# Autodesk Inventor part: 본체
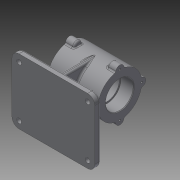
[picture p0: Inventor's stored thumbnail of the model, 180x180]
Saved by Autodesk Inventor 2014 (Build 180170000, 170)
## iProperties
Created: 2015-12
Part Number: 본체
Material: Generic
Document SubType Name: Modeling
Designer: test_25
Density: 1 g/cm^3
Appearance: Default
Author: test_25
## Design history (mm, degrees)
sketch "스케치3"
  geometry: L1 (-42.5, 37)-(42.5, 37); L2 (42.5, 37)-(42.5, 23.5); L3 (42.5, 23.5)-(20.5, 23.5); L4 (20.5, 23.5)-(20.5, 21); L5 (20.5, 21)-(-20.5, 21); L6 (-20.5, 21)-(-20.5, 23.5); L7 (-20.5, 23.5)-(-42.5, 23.5); L8 (-42.5, 23.5)-(-42.5, 37); L9 (-42.5, 0)-(42.5, 0); 2 further points
  constraints: 18 end point, 4 horizontal, 3 vertical, 2 perpendicular, 2 vertical alignment, 1 coincident, 1 midpoint
  dimensions: "d0" = 85 distance of L1.start L1.end; "d1" = 22 distance of L6.end L7.end; "d2" = 41 distance of L4.end L5.end; "d3" = 47 diameter of L7 L9; "d4" = 42 diameter of L5 L9; "d5" = 47 diameter of L3 L9; "d6" = 74 diameter of L1 L9
revolve "회전1" sketch "스케치3" stored, may be unused: angle "d7" = 90 deg
node "작업 평면1"
sketch "스케치4"
  geometry: L1 (-68, 55)-(48, 55); L2 (60, 43)-(60, -43); L3 (48, -55)-(-68, -55); L4 (-80, -43)-(-80, 43); A1 r 12 centre (-68, 43) between (-68, 55) and (-80, 43); A2 r 12 centre (-68, -43) between (-80, -43) and (-68, -55); A3 r 12 centre (48, -43) between (48, -55) and (60, -43); A4 r 12 centre (48, 43) between (60, 43) and (48, 55); 4 further points
  constraints: 8 end point, 8 point on circle, 8 tangent, 6 point on line, 4 centre point, 3 equal radius, 2 parallel, 1 horizontal, 1 perpendicular
  dimensions: "d9" = 140 distance of point (-80, 55) point (60, 55); "d10" = 110 distance of point (60, 55) point (60, -55); "d11" = 80 distance from line of L4 point (0, 0); "d12" = 55 distance from line of L1 point (0, 0); "d13" = 12 radius of A1
extrude "돌출1" join sketch "스케치4" distance "d14" = 10; taper "d15" = 0 deg
sketch "스케치6"
  geometry: L1 (25, -6)-(-25, -6); L2 (-25, -6)-(-25, 6); L3 (-25, 6)-(25, 6); L4 (25, 6)-(25, -6); L5 (4, -37)-(-4, -37); L6 (-4, -37)-(-4, 37); L7 (-4, 37)-(4, 37); L8 (4, 37)-(4, -37); L9 (4, -37)-(-4, 37); L10 (25, -6)-(-25, 6); 2 further points
  constraints: 20 end point, 4 parallel, 2 horizontal, 2 midpoint, 2 perpendicular, 1 coincident
  dimensions: "d21" = 50 distance of L2.end L3.end; "d22" = 8 distance of L6.end L7.end; "d23" = 12 distance of L1.end L2.end; "d26" = 74 distance of L5.end L6.end
extrude "돌출2" join sketch "스케치6" stored distance "d27" = 10; taper "d28" = 0 deg
sketch "스케치7"
  geometry: C1 r 7 at (0, 37); 1 further point
  constraints: 2 vertical alignment, 1 centre point, 1 other
  dimensions: "d31" = 14 diameter of C1
extrude "돌출4" join sketch "스케치7" distance "d32" = 15; taper "d33" = 0 deg
sketch "스케치13"
  geometry: L1 (-27.5, 37)-(42.5, 37) reference; 1 further point
sketch "스케치14"
  geometry: L1 (-27.5, 37)-(42.5, 37) reference; L2 (-27.5, 37)-(-27.5, 44); L3 (-27.5, 44)-(-30.048, 44); L4 (-30.048, 44)-(-27.5, 37); L5 (-42.5, 44)-(-27.5, 44) reference; L6 (-88, 0)-(108, 0) reference; 1 further point
  constraints: 6 end point, 2 perpendicular, 1 collinear
  dimensions: "d73" = 110 deg angle of L1 L4
revolve "회전2" stored, may be unused: angle "d74" = 20 deg
revolve "회전3" stored, may be unused: angle "d75" = 20 deg
sketch "스케치8"
  geometry: 2 further points
  constraints: 1 vertical alignment
  dimensions: "d34" = 37 distance of point (0, 0) point (0, -37)
hole "구멍1" sketch "스케치8" at (0, 0) diameter "d35" = 3.242; stored, may be unused: countersink angle "d39" = 90 deg, drill point angle "d41" = 118 deg; dims "d36" = 9, "d37" = 4, "d38" = 2, "d40" = 11
sketch "스케치9"
  geometry: C1 r 4 at (-48, 43); C2 r 4 at (68, 43); C3 r 4 at (68, -43); C4 r 4 at (-48, -43); A1 r 12 centre (68, 43) between (80, 43) and (68, 55) reference; A2 r 12 centre (-48, 43) between (-48, 55) and (-60, 43) reference; A3 r 12 centre (-48, -43) between (-60, -43) and (-48, -55) reference; A4 r 12 centre (68, -43) between (68, -55) and (80, -43) reference; 1 further point
  constraints: 4 centre point, 4 coincident, 3 equal radius
  dimensions: "d45" = 8 diameter of C1
extrude "돌출5" cut sketch "스케치9" stored distance "d46" = 15; taper "d47" = 0 deg
sketch "스케치17"
  geometry: L1 (68, -70)-(-48, -70) reference; L2 (-42.5, -37)-(42.5, -37) reference; L3 (-20.948, -37)-(-25, -70); 1 further point
  constraints: 2 end point, 2 point on line
  dimensions: "d94" = 97 deg angle of L1 L3; "d95" = 25 horizontal distance of point (0, 0) L3.end
feature "리브2" sketch "스케치17" dims "d96" = 1, "d97" = 12, "d98" = 0, "d99" = 0, "d100" = 1, "d101" = 1
chamfer "모따기1" distance "d62" = 1; stored, may be unused: second distance "d63" = 2, angle "d64" = 45 deg
fillet "모깎기4" dims "d65" = 0.3
fillet "모깎기5" dims "d79" = 3
fillet "모깎기6" dims "d80" = 3
sketch "스케치15"
  geometry: L1 (26.163, -26.163)-(0, 0); L2 (0, 0)-(0, -37); A1 r 37 centre (0, 0) between (26.163, -26.163) and (0, -37); 1 further point
  constraints: 4 end point, 2 point on circle, 1 centre point, 1 coincident, 1 vertical
  dimensions: "d84" = 74 diameter of A1; "d86" = 45 deg angle of L2 L1
fillet "모깎기11" dims "d102" = 3
fillet "모깎기12" dims "d103" = 3
fillet "모깎기13" dims "d104" = 3
chamfer "모따기2" distance "d105" = 1; stored, may be unused: second distance "d106" = 2, angle "d107" = 45 deg
fillet "모깎기14" dims "d108" = 3
sketch "스케치18"
  geometry: L1 (0, -37)-(0, 0); L2 (0, 0)-(26.163, -26.163); A1 r 37 centre (0, 0) between (0, -37) and (26.163, -26.163); 1 further point
  constraints: 4 end point, 2 point on circle, 1 centre point, 1 coincident, 1 vertical
  dimensions: "d109" = 74 diameter of A1; "d110" = 45 deg angle of L1 L2
node "작업 평면5"
  node "작업 평면4"
sketch "스케치19"
  geometry: 2 further points
  constraints: 1 coincident, 1 other
feature "엠보싱2" sketch "스케치19" dims "d0" = 85, "d1" = 22, "d2" = 41, "d3" = 47, "d4" = 42, "d5" = 47, "d6" = 74, "d112" = 0.5, "d113" = 0
fillet "모깎기15" dims "d114" = 3
node "솔리드1"
mirror "대칭6"
pattern_circular "원형 패턴3" dims "d77" = 360 deg
mirror "대칭4"
pattern_circular "원형 패턴4" dims angle "d82" = 360 deg
mirror "대칭5"
pattern_circular "원형 패턴2" dims angle "d70" = 360 deg
mirror "대칭3"
other parameters: "d111" = 0.5
